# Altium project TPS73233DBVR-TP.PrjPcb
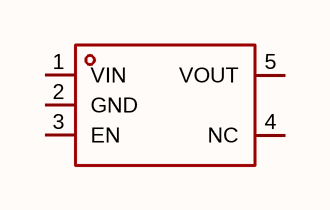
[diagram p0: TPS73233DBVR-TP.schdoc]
1 sheet, 1 parts. Net scope: global (net labels, ports and power ports of the same name join across sheets).

## Sheet TPS73233DBVR-TP.schdoc
size 127 x 101 mm

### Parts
U?  tps73233dbvr-tp  [SOT-23-5_L2.9-W1.6-P0.95-LS2.9-BL]  (value not drawn)

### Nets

Not connected (* = marked no-connect by the designer): U? 1(VIN) 2(GND) 3(EN) 4(NC) 5(VOUT)

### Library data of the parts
U? = tps73233dbvr-tp: 输出极性:正极;工作电压:5.5V;输出电压:3.3V;输出电流:250mA;电源纹波抑制比(PSRR):70dB@(1kHz);输出类型:固定;; Manufacturer: TECH PUBLIC(台舟); AddInBom: yes; ModelId: f208335ea6894ff1b04bfab971ca745a; ModelTransform: 114.173,114.173,0,0,0,0,0,-0.003,0; Output Configuration: 正极; Voltage - Supply: 5.5V; Output Voltage: 3.3V; Output Current: 250mA; Voltage Dropout: 180mV@(250mA); standby current: 10uA; Output Type: 固定; Number of Outputs: 1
